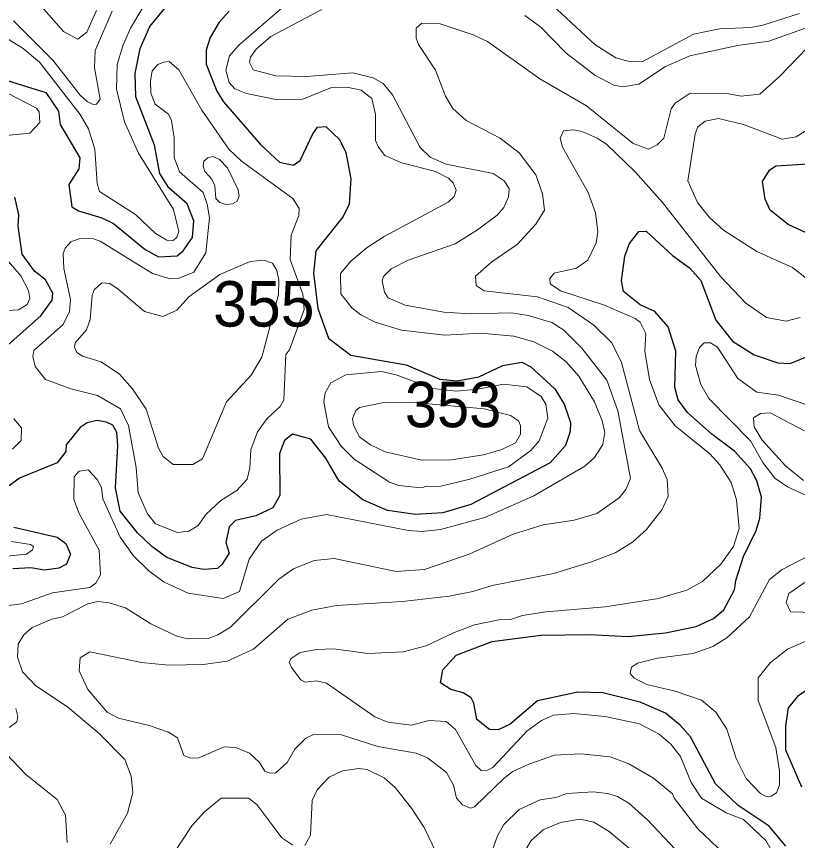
# Model space of a CAD drawing. Extents: x 673.6 to 698.9, y 7012 to 7040.1.
# Drawn here: x 682.54 to 683.915, y 7016.628 to 7018.078 of the extents above; entities that cross this region are included whole.
import ezdxf

# ---------------------------------------------------------------- set-up
doc = ezdxf.new("R2010")
doc.units = 0
doc.header["$LTSCALE"] = 0.032
doc.layers.add('1', color=7, linetype='Continuous', lineweight=25)
doc.layers.add('2', color=7, linetype='Continuous', lineweight=13)
doc.layers.add('21', color=7, linetype='Continuous')

msp = doc.modelspace()

# ---------------------------------------------------------------- linework, layer by layer
at = {"layer": '1'}
for points in [[(682.8229, 7017.6571), (682.8334, 7017.6658), (682.8499, 7017.6892), (682.8524, 7017.7185), (682.8409, 7017.7481), (682.8082, 7017.7763), (682.7929, 7017.8019), (682.7831, 7017.8519), (682.7506, 7017.9367), (682.749, 7017.9778), (682.7578, 7018.0218), (682.7748, 7018.0604), (682.827, 7018.1245)], [(682.9148, 7018.0872), (682.8972, 7018.0681), (682.8811, 7018.0411), (682.8739, 7018.0185), (682.8744, 7017.9939), (682.8927, 7017.9466), (682.9045, 7017.9278), (682.9695, 7017.853), (683.0032, 7017.8217), (683.028, 7017.8164), (683.0396, 7017.8244), (683.0617, 7017.8714), (683.0703, 7017.883), (683.0847, 7017.8844), (683.1089, 7017.8615), (683.12, 7017.8386), (683.1286, 7017.7921), (683.1261, 7017.7477), (683.1155, 7017.726), (683.0671, 7017.6659), (683.063, 7017.6264), (683.0705, 7017.5643)], [(682.5239, 7017.9655), (682.5918, 7017.9442), (682.6143, 7017.9114), (682.6171, 7017.8877), (682.652, 7017.8292), (682.6502, 7017.8099), (682.6324, 7017.7822), (682.6376, 7017.7431), (682.6496, 7017.7359)], [(683.9454, 7017.6906), (683.8983, 7017.7123), (683.8666, 7017.7375), (683.8579, 7017.7566), (683.8534, 7017.7877), (683.8657, 7017.8075), (683.8768, 7017.8155), (683.9814, 7017.8219)], [(682.51, 7017.4868), (682.5832, 7017.5511), (682.6034, 7017.5789), (682.6042, 7017.5912), (682.5914, 7017.6147), (682.5721, 7017.6302), (682.5504, 7017.66), (682.5436, 7017.7092), (682.5443, 7017.7292), (682.5373, 7017.7602)], [(682.6496, 7017.7359), (682.6906, 7017.7238), (682.7109, 7017.7138), (682.7667, 7017.6679), (682.79, 7017.6553), (682.8229, 7017.6571)], [(683.832, 7017.2822), (683.8041, 7017.3134), (683.7638, 7017.343), (683.7214, 7017.3814), (683.7049, 7017.4035), (683.699, 7017.4252), (683.7005, 7017.4893), (683.6873, 7017.532), (683.6636, 7017.5591), (683.6381, 7017.5704), (683.6088, 7017.5943), (683.6053, 7017.6134), (683.611, 7017.6565), (683.6194, 7017.6786), (683.6355, 7017.7), (683.6482, 7017.7003), (683.6949, 7017.6576), (683.7249, 7017.6358), (683.7446, 7017.6136), (683.7711, 7017.5439), (683.8006, 7017.5069), (683.8386, 7017.4828), (683.8801, 7017.4687), (683.902, 7017.4674), (683.9416, 7017.4838)], [(683.0705, 7017.5643), (683.0894, 7017.5121), (683.129, 7017.4819), (683.2264, 7017.4651), (683.2851, 7017.4398), (683.3159, 7017.4372), (683.3538, 7017.4442), (683.3965, 7017.4638), (683.4299, 7017.4695), (683.4458, 7017.4618), (683.4877, 7017.4227), (683.5042, 7017.3956), (683.5156, 7017.3635), (683.5148, 7017.3479), (683.5063, 7017.323), (683.4795, 7017.2925), (683.3397, 7017.2194), (683.2909, 7017.2049), (683.2428, 7017.2017), (683.193, 7017.2085), (683.1496, 7017.2274), (683.1084, 7017.2605), (683.0849, 7017.3006), (683.0581, 7017.3345), (683.0263, 7017.3429), (683.0123, 7017.3317), (683.0031, 7017.3089), (683.0037, 7017.235), (682.9915, 7017.2136), (682.9614, 7017.1994), (682.926, 7017.1911), (682.9147, 7017.18), (682.9085, 7017.1525), (682.9146, 7017.134), (682.9026, 7017.1146), (682.8942, 7017.1069), (682.8702, 7017.1048), (682.8494, 7017.1085), (682.8047, 7017.1261), (682.7786, 7017.1453), (682.7533, 7017.1693), (682.7231, 7017.2076), (682.7145, 7017.2489), (682.7185, 7017.3229), (682.7169, 7017.3459), (682.7101, 7017.3589), (682.6988, 7017.3641), (682.6818, 7017.3671), (682.6648, 7017.3631), (682.6526, 7017.355), (682.6275, 7017.3241), (682.6271, 7017.3124), (682.6117, 7017.2929), (682.5456, 7017.2659), (682.5274, 7017.252)], [(683.8199, 7017.1277), (683.8418, 7017.1734), (683.8485, 7017.1955), (683.8516, 7017.232), (683.8433, 7017.2612), (683.832, 7017.2822)], [(682.5358, 7017.1797), (682.6117, 7017.1616), (682.627, 7017.1509), (682.6354, 7017.1322), (682.6282, 7017.1141), (682.6146, 7017.1074), (682.5899, 7017.104), (682.5657, 7017.108), (682.5342, 7017.1061)], [(683.8945, 7016.6182), (683.8649, 7016.6536), (683.8104, 7016.6897), (683.7707, 7016.7281), (683.7268, 7016.8105), (683.7085, 7016.8313), (683.6825, 7016.8524), (683.6378, 7016.8714), (683.5724, 7016.8877), (683.5281, 7016.8894), (683.4573, 7016.8738), (683.4089, 7016.8331), (683.388, 7016.8229), (683.3727, 7016.8237), (683.3507, 7016.841), (683.3455, 7016.8697), (683.3407, 7016.8792), (683.3267, 7016.8877), (683.3046, 7016.8936), (683.2868, 7016.9053), (683.2905, 7016.9284), (683.3139, 7016.9545), (683.3772, 7016.9782), (683.463, 7016.9896), (683.5481, 7016.9905), (683.6167, 7016.9872), (683.6825, 7016.9938), (683.7362, 7017.0047), (683.7671, 7017.0188), (683.7852, 7017.0341), (683.8038, 7017.0694), (683.806, 7017.0859), (683.8199, 7017.1277)], [(683.9603, 7016.9132), (683.9146, 7016.8815), (683.8981, 7016.8613), (683.8937, 7016.8298), (683.8935, 7016.7877), (683.922, 7016.7227)]]:
    msp.add_lwpolyline(points, dxfattribs=at)
at = {"layer": '2'}
for points in [[(683.1289, 7017.6473), (683.1576, 7017.6713), (683.1877, 7017.6908), (683.3001, 7017.7511), (683.3108, 7017.7612), (683.3143, 7017.7723), (683.3089, 7017.7855), (683.3009, 7017.7934), (683.2776, 7017.8052), (683.2183, 7017.8204), (683.1887, 7017.8337), (683.1773, 7017.8482), (683.1723, 7017.8601), (683.1721, 7017.9054), (683.1657, 7017.9335), (683.1467, 7017.9485), (683.1217, 7017.9536), (683.0947, 7017.9529), (683.0444, 7017.9323), (682.9997, 7017.9315), (682.945, 7017.9424), (682.9247, 7017.9508), (682.9145, 7017.9621), (682.9086, 7017.9837), (682.9152, 7018.0088), (682.9317, 7018.0278), (683.0423, 7018.1236)], [(682.7774, 7018.1193), (682.7413, 7018.0574), (682.7275, 7018.0262), (682.7178, 7017.9938), (682.7162, 7017.95), (682.7307, 7017.8926), (682.7549, 7017.8375), (682.8165, 7017.7385), (682.8262, 7017.7), (682.8226, 7017.6895), (682.8159, 7017.6841), (682.8049, 7017.6842), (682.7849, 7017.6959), (682.7501, 7017.7298), (682.6865, 7017.7701), (682.6824, 7017.7839), (682.6783, 7017.8443), (682.6669, 7017.8801), (682.6526, 7017.9054), (682.5808, 7017.9977), (682.552, 7018.0216), (682.4913, 7018.0594)], [(683.4675, 7018.1136), (683.5582, 7018.0286), (683.5951, 7018.0055), (683.6184, 7017.9988), (683.6412, 7017.9981), (683.7318, 7018.0472), (683.7778, 7018.0563), (683.8324, 7018.0586), (683.8539, 7018.0626), (683.9184, 7018.0832)], [(682.5846, 7018.0957), (682.623, 7018.0517), (682.6484, 7018.0384), (682.6642, 7018.0506), (682.6814, 7018.0885)], [(682.7088, 7018.0875), (682.6791, 7018.0182), (682.6775, 7017.9876), (682.6879, 7017.9324), (682.6814, 7017.9238), (682.6756, 7017.9233), (682.665, 7017.9284), (682.6527, 7017.9398), (682.6041, 7018.0014), (682.5351, 7018.0705)], [(683.3369, 7017.1317), (683.4144, 7017.1672), (683.4672, 7017.1836), (683.5218, 7017.1919), (683.5619, 7017.2038), (683.6011, 7017.2313), (683.6128, 7017.2456), (683.6207, 7017.2652), (683.5986, 7017.3841), (683.579, 7017.438), (683.5352, 7017.4945), (683.5036, 7017.526), (683.4822, 7017.5396), (683.4406, 7017.5518), (683.4117, 7017.5566), (683.3385, 7017.5551), (683.2923, 7017.5575), (683.2244, 7017.5698), (683.1947, 7017.583), (683.188, 7017.5927), (683.1838, 7017.6128), (683.1863, 7017.6208), (683.1996, 7017.6342), (683.2297, 7017.6495), (683.3121, 7017.678), (683.3519, 7017.7024), (683.3863, 7017.7282), (683.3983, 7017.7418), (683.4064, 7017.7606), (683.4072, 7017.7754), (683.3985, 7017.7887), (683.3792, 7017.8015), (683.2964, 7017.8179), (683.2681, 7017.8307), (683.2507, 7017.8478), (683.2022, 7017.9402), (683.1855, 7017.96), (683.1678, 7017.9702), (683.1321, 7017.9791), (683.0509, 7017.9725), (682.9968, 7017.9734), (682.9569, 7017.9842), (682.9504, 7017.9971), (682.9524, 7018.0063), (682.9621, 7018.0204), (682.9878, 7018.0427), (683.0775, 7018.0902)], [(683.435, 7018.0797), (683.4633, 7018.0594), (683.5072, 7018.0139), (683.5581, 7017.9749), (683.5918, 7017.957), (683.6074, 7017.9545), (683.6358, 7017.959), (683.6828, 7017.9899), (683.7252, 7018.0086), (683.8091, 7018.0267), (683.8646, 7018.0349), (683.9982, 7018.0822)], [(683.9474, 7018.0392), (683.8829, 7017.9724), (683.8484, 7017.9415), (683.8159, 7017.938), (683.7942, 7017.942), (683.7258, 7017.9429), (683.6998, 7017.9257), (683.6922, 7017.9153), (683.6794, 7017.8637), (683.6679, 7017.8523), (683.6527, 7017.8444), (683.6256, 7017.8548), (683.5434, 7017.9211), (683.4616, 7017.9685), (683.3691, 7018.0343), (683.344, 7018.0459), (683.286, 7018.065), (683.2536, 7018.066), (683.244, 7018.0573), (683.2438, 7018.0399), (683.248, 7018.029), (683.2776, 7017.9835), (683.2956, 7017.9377), (683.308, 7017.9164), (683.3317, 7017.8953), (683.3913, 7017.8642), (683.425, 7017.838), (683.4542, 7017.7996), (683.4663, 7017.7658), (683.4696, 7017.737), (683.4545, 7017.7129)], [(683.9298, 7017.6175), (683.906, 7017.6363), (683.8435, 7017.6643), (683.7846, 7017.7022), (683.7602, 7017.7246), (683.7391, 7017.7505), (683.722, 7017.7888), (683.735, 7017.8716), (683.7396, 7017.884), (683.7525, 7017.894), (683.7756, 7017.8986), (683.8199, 7017.888), (683.888, 7017.8624), (683.9123, 7017.866), (683.9282, 7017.8764)], [(683.8123, 7017.177), (683.8075, 7017.2277), (683.7981, 7017.2581), (683.7784, 7017.2891), (683.7606, 7017.3085), (683.6998, 7017.3576), (683.671, 7017.3945), (683.6543, 7017.4395), (683.6464, 7017.4893), (683.648, 7017.5201), (683.6381, 7017.5402), (683.629, 7017.5469), (683.5751, 7017.5701), (683.4975, 7017.5951), (683.4797, 7017.6077), (683.4788, 7017.6172), (683.4868, 7017.6263), (683.526, 7017.6354), (683.5456, 7017.6491), (683.5607, 7017.6796), (683.5632, 7017.6989), (683.5593, 7017.7325), (683.5464, 7017.7681), (683.5015, 7017.8483), (683.4969, 7017.8637), (683.5029, 7017.8767), (683.5205, 7017.8786), (683.5356, 7017.8757), (683.5622, 7017.8642), (683.5789, 7017.8533), (683.6299, 7017.8041), (683.6773, 7017.7509), (683.78, 7017.6202), (683.8241, 7017.5736), (683.8603, 7017.5483), (683.8948, 7017.542), (683.9193, 7017.5486)], [(683.4545, 7017.7129), (683.4214, 7017.6769), (683.3768, 7017.6462), (683.3479, 7017.6214), (683.3494, 7017.6044), (683.3632, 7017.5951)], [(682.4929, 7017.6853), (682.5481, 7017.6217), (682.5617, 7017.5958), (682.5639, 7017.5821), (682.5589, 7017.5711), (682.5437, 7017.5619), (682.4934, 7017.5591)], [(683.1713, 7017.5401), (683.1462, 7017.553), (683.1304, 7017.5656), (683.1113, 7017.5899), (683.1105, 7017.6258), (683.1289, 7017.6473)], [(683.3632, 7017.5951), (683.457, 7017.5847), (683.511, 7017.566), (683.5562, 7017.5351), (683.588, 7017.5041), (683.6053, 7017.4693), (683.6366, 7017.3493), (683.6769, 7017.2835), (683.6856, 7017.2633), (683.6874, 7017.2341), (683.6765, 7017.2106), (683.6483, 7017.1748), (683.6242, 7017.1529), (683.5941, 7017.1345), (683.5522, 7017.1182), (683.4857, 7017.0982), (683.3772, 7017.0768), (683.3436, 7017.066), (683.302, 7017.058), (683.2195, 7017.0484), (683.1037, 7017.0414), (683.06, 7017.0337), (683.0178, 7017.0176), (682.9577, 7016.965), (682.9113, 7016.9437), (682.8697, 7016.9379), (682.8083, 7016.9366), (682.7602, 7016.9412), (682.6693, 7016.9602), (682.6524, 7016.9496), (682.6506, 7016.9267), (682.6661, 7016.894), (682.6997, 7016.854), (682.7198, 7016.8434), (682.7736, 7016.8307), (682.8081, 7016.8187), (682.8238, 7016.8085), (682.8347, 7016.7775), (682.8474, 7016.7731), (682.8612, 7016.7738), (682.9058, 7016.7931), (682.9262, 7016.7917), (682.9503, 7016.782), (682.9679, 7016.7651), (682.9773, 7016.75), (682.9861, 7016.7465), (682.9967, 7016.7472), (683.0166, 7016.7654), (683.0304, 7016.7886), (683.0493, 7016.8081), (683.0632, 7016.8146), (683.1126, 7016.8138), (683.176, 7016.7937), (683.2437, 7016.7817), (683.2634, 7016.7735), (683.297, 7016.748), (683.3093, 7016.7253), (683.3147, 7016.7026), (683.3251, 7016.6907), (683.3395, 7016.6848), (683.3462, 7016.6871), (683.3987, 7016.738), (683.414, 7016.7493), (683.4422, 7016.7627), (683.4874, 7016.7784), (683.5336, 7016.7809), (683.5852, 7016.7752), (683.6181, 7016.763), (683.6614, 7016.738), (683.6946, 7016.7104), (683.6983, 7016.7019), (683.7396, 7016.6487), (683.809, 7016.5821)], [(682.4974, 7017.0381), (682.5489, 7017.0448), (682.6039, 7017.0639), (682.6694, 7017.0734), (682.68, 7017.0809), (682.6883, 7017.0958), (682.6857, 7017.1389), (682.6509, 7017.2037), (682.6413, 7017.2284), (682.642, 7017.2678), (682.6504, 7017.278), (682.6666, 7017.2803), (682.6826, 7017.2631), (682.6898, 7017.2494), (682.6924, 7017.2292), (682.7229, 7017.1618), (682.7463, 7017.1288), (682.7732, 7017.1025), (682.8003, 7017.0824), (682.8426, 7017.0634), (682.9043, 7017.0538), (682.933, 7017.0665), (682.9497, 7017.1231), (682.9716, 7017.1547), (682.9993, 7017.1744), (683.0412, 7017.1933), (683.0859, 7017.2016), (683.2302, 7017.1738), (683.2539, 7017.1721), (683.2868, 7017.1755), (683.3646, 7017.1965), (683.451, 7017.2347), (683.5406, 7017.2866), (683.5575, 7017.302), (683.5724, 7017.3249), (683.5756, 7017.3463), (683.5713, 7017.3668), (683.5578, 7017.4002), (683.5302, 7017.4452), (683.5077, 7017.4701), (683.4839, 7017.4891), (683.451, 7017.5056), (683.4159, 7017.5157), (683.3576, 7017.5206), (683.2943, 7017.5173), (683.2181, 7017.5261), (683.1713, 7017.5401)], [(683.9328, 7017.394), (683.8814, 7017.4119), (683.843, 7017.4169), (683.8096, 7017.4411), (683.7742, 7017.4959), (683.7615, 7017.5041), (683.7506, 7017.504), (683.7423, 7017.4954), (683.7364, 7017.4797), (683.7354, 7017.464), (683.7448, 7017.4305)], [(683.7448, 7017.4305), (683.759, 7017.406), (683.832, 7017.3315), (683.8538, 7017.2935), (683.875, 7017.2656), (683.8971, 7017.2505)], [(682.5334, 7017.3165), (682.5484, 7017.3319), (682.5492, 7017.3543), (682.5359, 7017.37)], [(683.9251, 7017.2613), (683.8938, 7017.2873), (683.8526, 7017.3328), (683.8387, 7017.3562), (683.8372, 7017.3717), (683.8495, 7017.3796), (683.867, 7017.3808), (683.9273, 7017.3487)], [(683.8971, 7017.2505), (683.9368, 7017.2322)], [(683.6701, 7017.0539), (683.72, 7017.0684), (683.7477, 7017.0836), (683.78, 7017.1143), (683.8022, 7017.1455), (683.8123, 7017.177)], [(682.5059, 7017.1264), (682.5579, 7017.1318), (682.5687, 7017.1394), (682.5704, 7017.1457), (682.5649, 7017.1491), (682.5318, 7017.1542)], [(683.0281, 7017.106), (683.0642, 7017.121), (683.0993, 7017.1244), (683.2084, 7017.1015), (683.2582, 7017.1047), (683.3369, 7017.1317)], [(683.9379, 7017.1307), (683.8879, 7017.1047), (683.8655, 7017.0871), (683.8301, 7017.0216), (683.7904, 7016.9848), (683.7656, 7016.9696), (683.7314, 7016.9572), (683.6685, 7016.9492), (683.6333, 7016.9403), (683.6229, 7016.9331), (683.6205, 7016.9217), (683.6272, 7016.9135), (683.6496, 7016.9026), (683.6997, 7016.8908), (683.7459, 7016.8749), (683.7712, 7016.854), (683.7907, 7016.824), (683.8067, 7016.7724), (683.8242, 7016.7372), (683.8497, 7016.7106), (683.8595, 7016.7054), (683.8684, 7016.7064), (683.8779, 7016.7121), (683.883, 7016.7262), (683.883, 7016.7502), (683.8766, 7016.7916), (683.8456, 7016.8745), (683.8453, 7016.9145), (683.8668, 7016.9406), (683.8972, 7016.9648), (683.9386, 7016.983)], [(682.7054, 7016.6215), (682.7359, 7016.676), (682.7449, 7016.7126), (682.7424, 7016.7415), (682.7311, 7016.7707), (682.6863, 7016.8157), (682.6304, 7016.8633), (682.5742, 7016.9005), (682.551, 7016.9248), (682.5422, 7016.951), (682.5436, 7016.9737), (682.5535, 7016.9903), (682.5681, 7017.0028), (682.6024, 7017.0175), (682.6211, 7017.0219), (682.6662, 7017.0444), (682.6836, 7017.0488), (682.7033, 7017.0463), (682.7325, 7017.0373), (682.7766, 7017.0096), (682.8223, 7016.9874), (682.8423, 7016.9832), (682.8778, 7016.9837), (682.8946, 7016.9898), (682.9171, 7017.0035), (683.0023, 7017.0878), (683.0281, 7017.106)], [(683.946, 7017.0291), (683.9027, 7017.0302), (683.8946, 7017.0472), (683.8993, 7017.0625), (683.9303, 7017.0839)], [(683.8779, 7016.5955), (683.8588, 7016.6284), (683.8195, 7016.665), (683.7891, 7016.6771), (683.7458, 7016.7029), (683.7277, 7016.7301), (683.709, 7016.7757), (683.6921, 7016.7977), (683.6713, 7016.8152), (683.6365, 7016.8335), (683.5761, 7016.8466), (683.5213, 7016.8517), (683.4857, 7016.8484), (683.4643, 7016.8395), (683.4387, 7016.8207), (683.3787, 7016.7566), (683.369, 7016.7516), (683.3582, 7016.7515), (683.3489, 7016.7599), (683.3127, 7016.8237), (683.2967, 7016.8373), (683.2664, 7016.8392), (683.2353, 7016.8311), (683.1941, 7016.8361), (683.1709, 7016.8456), (683.0861, 7016.9048), (683.0685, 7016.909), (683.0482, 7016.9068), (683.0407, 7016.9111), (683.0241, 7016.9325), (683.0204, 7016.9419), (683.024, 7016.9481), (683.0395, 7016.9589), (683.0686, 7016.9642), (683.0987, 7016.9651), (683.1587, 7016.9569), (683.2211, 7016.9602), (683.2614, 7016.9706), (683.3094, 7016.9937), (683.3465, 7017.0074), (683.3892, 7017.0166), (683.41, 7017.0169), (683.4311, 7017.0241), (683.4718, 7017.0307), (683.5764, 7017.039), (683.6701, 7017.0539)], [(682.5277, 7016.8271), (682.5408, 7016.8369), (682.5426, 7016.8466), (682.539, 7016.8603)], [(682.5107, 7016.7924), (682.5569, 7016.7445), (682.612, 7016.7002), (682.6267, 7016.6728), (682.6295, 7016.6245)], [(683.2787, 7016.6072), (683.2576, 7016.6511), (683.2358, 7016.685), (683.2065, 7016.7212), (683.1872, 7016.7386), (683.1577, 7016.7528), (683.1427, 7016.7546), (683.1142, 7016.7506), (683.0908, 7016.7395), (683.0693, 7016.7173), (683.0605, 7016.6986), (683.0579, 7016.6378), (683.0477, 7016.6191)], [(683.0266, 7016.62), (683.0072, 7016.6331), (682.9634, 7016.6913), (682.9489, 7016.7025), (682.9005, 7016.7028), (682.8712, 7016.6788), (682.8491, 7016.6542), (682.7968, 7016.5749)], [(683.7084, 7016.6037), (683.6515, 7016.664), (683.6178, 7016.6936), (683.5979, 7016.7056), (683.5806, 7016.711), (683.555, 7016.7135), (683.509, 7016.7111), (683.4895, 7016.7037), (683.4619, 7016.6994), (683.4251, 7016.6829), (683.398, 7016.6561), (683.3868, 7016.6366), (683.3643, 7016.5735)], [(683.4112, 7016.5407), (683.4334, 7016.6064), (683.4461, 7016.6284), (683.4672, 7016.6469), (683.498, 7016.6597), (683.5321, 7016.6658)], [(683.5321, 7016.6658), (683.5566, 7016.6601), (683.5833, 7016.6442), (683.6603, 7016.5796)]]:
    msp.add_lwpolyline(points, dxfattribs=at)
for points in [[(682.5066, 7017.9565), (682.4874, 7017.9644), (682.4674, 7017.9788), (682.4254, 7018.0339), (682.4112, 7018.0374), (682.3996, 7018.0315), (682.3943, 7018.0237), (682.3964, 7017.9832), (682.3883, 7017.9646), (682.364, 7017.9368), (682.3635, 7017.9275), (682.3829, 7017.9077), (682.4111, 7017.8918), (682.4393, 7017.8574), (682.4623, 7017.847), (682.4864, 7017.8501), (682.5014, 7017.861), (682.5223, 7017.8685), (682.5636, 7017.873), (682.5812, 7017.8915), (682.5801, 7017.9103), (682.5754, 7017.9168), (682.5248, 7017.9433)], [(682.7509, 7017.2846), (682.7543, 7017.2397), (682.7711, 7017.2028), (682.7852, 7017.1853), (682.8239, 7017.1698), (682.8436, 7017.1727), (682.8596, 7017.1816), (682.8739, 7017.2024), (682.9002, 7017.2263), (682.9284, 7017.2438), (682.9461, 7017.2637), (682.9511, 7017.2839), (682.9529, 7017.3156), (682.9647, 7017.3472), (682.9814, 7017.3707), (683.0045, 7017.3916), (683.0109, 7017.4035), (683.0144, 7017.4835), (683.0206, 7017.4916), (683.0465, 7017.5626), (683.0442, 7017.5895), (683.0219, 7017.6503), (683.024, 7017.6935), (683.0375, 7017.7279), (683.0376, 7017.7403), (683.0267, 7017.7579), (682.9361, 7017.8232), (682.9139, 7017.8445), (682.8666, 7017.913), (682.8259, 7017.9843), (682.8088, 7017.9986), (682.7992, 7017.9975), (682.789, 7017.9933), (682.7794, 7017.9819), (682.7764, 7017.9651), (682.777, 7017.9433), (682.7846, 7017.9239), (682.8078, 7017.9061), (682.8131, 7017.8952), (682.818, 7017.8648), (682.8181, 7017.83), (682.8272, 7017.8049), (682.8686, 7017.7681), (682.8762, 7017.7476), (682.8803, 7017.7236), (682.8736, 7017.6621), (682.8525, 7017.6283), (682.8248, 7017.6171), (682.8109, 7017.6167), (682.7799, 7017.6259), (682.6876, 7017.6827), (682.6743, 7017.6873), (682.6536, 7017.6882), (682.636, 7017.6813), (682.6259, 7017.6701), (682.6225, 7017.6608), (682.6234, 7017.6348), (682.6356, 7017.5801), (682.6339, 7017.5587), (682.6223, 7017.5358), (682.5709, 7017.4902), (682.5691, 7017.4798), (682.5731, 7017.4624), (682.5916, 7017.4391), (682.636, 7017.4226), (682.6832, 7017.4112), (682.7237, 7017.3878), (682.7374, 7017.3582)], [(682.8841, 7017.7918), (682.8717, 7017.8054), (682.8687, 7017.8146), (682.8702, 7017.8236), (682.8772, 7017.8294), (682.8858, 7017.8318), (682.8977, 7017.8262), (682.9115, 7017.8117), (682.9305, 7017.7733), (682.932, 7017.7618), (682.929, 7017.7528), (682.9206, 7017.7485), (682.9087, 7017.7474), (682.8985, 7017.7506), (682.8909, 7017.7578), (682.8894, 7017.7801)], [(682.9721, 7017.4783), (682.9531, 7017.447), (682.9102, 7017.4), (682.868, 7017.2996), (682.8509, 7017.2897), (682.816, 7017.2897), (682.7987, 7017.3036), (682.7905, 7017.3185), (682.7688, 7017.3871), (682.7446, 7017.423), (682.7216, 7017.4484), (682.6894, 7017.4701), (682.6565, 7017.4803), (682.6468, 7017.487), (682.6422, 7017.4961), (682.6434, 7017.5036), (682.6633, 7017.5268), (682.67, 7017.5449), (682.6735, 7017.5879), (682.6771, 7017.597), (682.6908, 7017.6091), (682.7049, 7017.6084), (682.7192, 7017.5985), (682.7656, 7017.5587), (682.7981, 7017.5502), (682.8226, 7017.5613), (682.8435, 7017.5846), (682.8983, 7017.6239), (682.9516, 7017.6469), (682.9758, 7017.6495), (682.9909, 7017.6442), (682.9986, 7017.6309), (683.0021, 7017.6142), (683.0013, 7017.5887)], [(683.2733, 7017.4233), (683.3139, 7017.419), (683.3522, 7017.4221), (683.3974, 7017.4309), (683.4385, 7017.4263), (683.464, 7017.4093), (683.472, 7017.3961), (683.4753, 7017.3715), (683.4604, 7017.3315), (683.4453, 7017.3145), (683.4061, 7017.2859), (683.3379, 7017.2639), (683.2847, 7017.2513), (683.2627, 7017.2516), (683.2524, 7017.2485), (683.2135, 7017.2529), (683.1966, 7017.2588), (683.1347, 7017.2993), (683.1117, 7017.3222), (683.0892, 7017.3562), (683.081, 7017.4), (683.0836, 7017.4156), (683.0934, 7017.4334), (683.1201, 7017.4473), (683.1829, 7017.4531), (683.2102, 7017.4468)], [(683.41, 7017.376), (683.4236, 7017.3668), (683.4271, 7017.3582), (683.4271, 7017.3429), (683.4183, 7017.3276), (683.3947, 7017.3161), (683.362, 7017.3065), (683.3059, 7017.2979), (683.2536, 7017.2974), (683.1891, 7017.312), (683.1631, 7017.3243), (683.1439, 7017.3385), (683.1334, 7017.3592), (683.1319, 7017.3707), (683.1377, 7017.3849), (683.1441, 7017.3902), (683.1871, 7017.3989), (683.2329, 7017.3997), (683.3633, 7017.3875)]]:
    msp.add_lwpolyline(points, close=True, dxfattribs=at)

# ---------------------------------------------------------------- texts
at = {"layer": '21'}
msp.add_text('355', height=0.08, dxfattribs=at).set_placement((682.8864, 7017.5324))
at = {"layer": '21', "width": 0.95}
msp.add_text('353', height=0.08, dxfattribs=at).set_placement((683.2239, 7017.3553))

doc.saveas('drawing.dxf')
